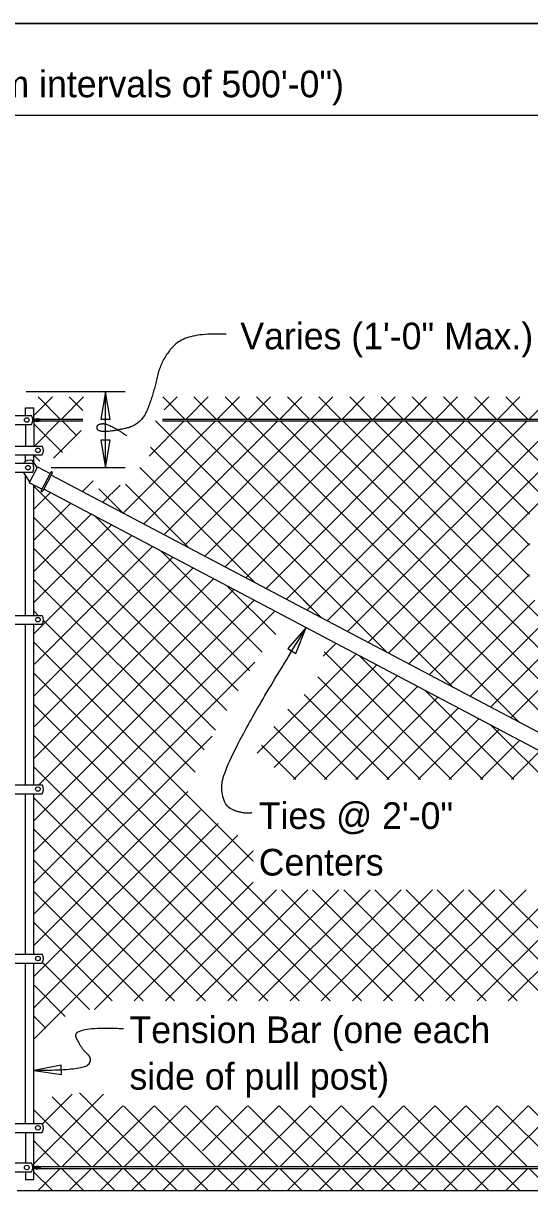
# Model space of a CAD drawing. Extents: x 0 to 41.2, y 0 to 26.
# Drawn here: x 12.4 to 16.23, y 17.08 to 25.96 of the extents above; entities that cross this region are included whole.
import ezdxf

# ---------------------------------------------------------------- set-up
doc = ezdxf.new("R2010")
doc.units = 0
for name, color, linetype in [('ActivePts-ConstElements', 7, 'Continuous'), ('Dimension', 7, 'Continuous'), ('Miscellaneous', 7, 'Continuous'), ('Miscellaneous1', 7, 'Continuous'), ('SteelMisc', 7, 'Continuous'), ('SupstrConc', 7, 'Continuous'), ('TextStructures', 7, 'Continuous')]:
    doc.layers.add(name, color=color, linetype=linetype)

msp = doc.modelspace()

# ---------------------------------------------------------------- linework, layer by layer
at = {"layer": 'ActivePts-ConstElements'}
msp.add_lwpolyline([(0, 0), (41.2106, 0), (41.2106, 25.96), (0, 25.96)], close=True, dxfattribs=at)
at = {"layer": 'Dimension'}
for p, q in [((2.2062, 25.2672), (22.2062, 25.2672)), ((13.1684, 23.1761), (12.4194, 23.1761)), ((13.0184, 22.6012), (13.0184, 23.1761)), ((13.1684, 22.6012), (12.6093, 22.6012))]:
    msp.add_line(p, q, dxfattribs=at)
for points in [[(13.0184, 23.1761), (12.9832, 22.9678), (13.0537, 22.9678)], [(13.0184, 22.6012), (13.0537, 22.8095), (12.9832, 22.8095)], [(14.5361, 21.3922), (14.3971, 21.2332), (14.4572, 21.1963)], [(12.4771, 18.0429), (12.6863, 18.0139), (12.6842, 18.0844)]]:
    msp.add_lwpolyline(points, close=True, dxfattribs=at)
for points in [[(13.9321, 23.6099), (13.634, 23.6259), (13.4393, 23.4234), (13.3796, 23.1471), (13.2873, 22.9252), (13.0658, 22.8744), (12.9551, 22.8744), (12.9551, 22.9344), (13.0474, 22.9344), (13.1812, 22.842)], [(14.1244, 19.9926), (14.0777, 19.9785), (13.8948, 20.0458), (13.9033, 20.3724), (14.5362, 21.3922)], [(13.1545, 18.3586), (12.7557, 18.3765), (12.8361, 18.2097), (12.9224, 18.1322), (12.8539, 18.0428), (12.4771, 18.0428)]]:
    msp.add_open_spline(points, degree=2, dxfattribs=at)
at = {"layer": 'Miscellaneous'}
for p, q in [((12.4771, 22.996), (12.6172, 23.1361)), ((12.5097, 23.1361), (12.6764, 22.9695)), ((12.6862, 22.9695), (12.8529, 23.1361)), ((12.7454, 23.1361), (12.8477, 23.0339)), ((13.4525, 23.1361), (13.6192, 22.9695)), ((13.463, 23.0391), (13.56, 23.1361)), ((13.629, 22.9695), (13.7957, 23.1361)), ((13.6882, 23.1361), (13.8549, 22.9695)), ((13.8647, 22.9695), (14.0314, 23.1361)), ((13.9239, 23.1361), (14.0906, 22.9695)), ((14.1004, 22.9695), (14.2671, 23.1361)), ((14.1597, 23.1361), (14.3263, 22.9695)), ((14.3361, 22.9695), (14.5028, 23.1361)), ((14.3954, 23.1361), (14.562, 22.9695)), ((14.5718, 22.9695), (14.7385, 23.1361)), ((14.6311, 23.1361), (14.7977, 22.9695)), ((14.8075, 22.9695), (14.9742, 23.1361)), ((14.8668, 23.1361), (15.0334, 22.9695)), ((15.0432, 22.9695), (15.2099, 23.1361)), ((15.1025, 23.1361), (15.2691, 22.9695)), ((15.2789, 22.9695), (15.4456, 23.1361)), ((15.3382, 23.1361), (15.5048, 22.9695)), ((15.5146, 22.9695), (15.6813, 23.1361)), ((15.5739, 23.1361), (15.7405, 22.9695)), ((15.7503, 22.9695), (15.917, 23.1361)), ((15.8096, 23.1361), (15.9762, 22.9695)), ((15.986, 22.9695), (16.1527, 23.1361)), ((16.0453, 23.1361), (16.2119, 22.9695)), ((16.2217, 22.9695), (16.3884, 23.1361)), ((12.4771, 22.9331), (12.6938, 22.7164)), ((12.4821, 22.7653), (12.6715, 22.9547)), ((12.6912, 22.9547), (12.7998, 22.8461)), ((13.1537, 22.2584), (13.85, 22.9547)), ((13.3079, 22.177), (14.0857, 22.9547)), ((13.3487, 22.6891), (13.6143, 22.9547)), ((13.3983, 22.9547), (15.1489, 21.2041)), ((13.4621, 22.0955), (14.3214, 22.9547)), ((13.6163, 22.014), (14.5571, 22.9547)), ((13.634, 22.9547), (15.6487, 20.94)), ((13.7706, 21.9325), (14.7928, 22.9547)), ((13.8697, 22.9547), (16.1486, 20.6758)), ((13.9248, 21.851), (15.0285, 22.9547)), ((14.079, 21.7695), (15.2642, 22.9547)), ((14.1054, 22.9547), (16.6484, 20.4117)), ((14.2332, 21.688), (15.4999, 22.9547)), ((14.3411, 22.9547), (17.1483, 20.1475)), ((14.3874, 21.6065), (15.7356, 22.9547)), ((14.5416, 21.525), (15.9713, 22.9547)), ((14.5768, 22.9547), (17.4573, 20.0742)), ((14.6958, 21.4435), (16.207, 22.9547)), ((14.8125, 22.9547), (17.4573, 20.3099)), ((14.85, 21.362), (16.4427, 22.9547)), ((15.0042, 21.2805), (16.6784, 22.9547)), ((15.0482, 22.9547), (16.224, 21.7789)), ((15.1584, 21.199), (16.9141, 22.9547)), ((15.2839, 22.9547), (16.224, 22.0146)), ((15.5196, 22.9547), (16.224, 22.2503)), ((15.7553, 22.9547), (16.393, 22.317)), ((15.991, 22.9547), (16.6287, 22.317)), ((12.625, 22.6726), (12.8347, 22.8823)), ((13.3596, 22.7577), (14.649, 21.4683)), ((12.4771, 22.6974), (12.5225, 22.6519)), ((13.2788, 22.6027), (14.1492, 21.7324)), ((12.4771, 22.4617), (14.0233, 20.9155)), ((12.8453, 22.4214), (12.9257, 22.5019)), ((12.9995, 22.3399), (13.1301, 22.4705)), ((13.1699, 22.476), (13.6493, 21.9966)), ((12.4771, 22.2889), (12.6023, 22.4142)), ((12.9688, 22.4413), (13.1494, 22.2607)), ((12.4771, 22.0532), (12.7565, 22.3327)), ((12.4771, 21.8175), (12.9108, 22.2512)), ((12.4771, 22.226), (13.9369, 20.7661)), ((12.9373, 22.2372), (14.1096, 21.0648)), ((12.4771, 21.5818), (13.065, 22.1697)), ((12.4771, 21.3461), (13.2192, 22.0882)), ((15.3127, 21.1175), (16.224, 22.0289)), ((12.4771, 21.9903), (13.8506, 20.6168)), ((12.4771, 20.8747), (13.5276, 21.9252)), ((12.4835, 21.1168), (13.3734, 22.0067)), ((13.4371, 21.973), (14.2041, 21.206)), ((12.4771, 20.639), (13.6818, 21.8437)), ((12.4771, 20.4033), (13.836, 21.7622)), ((12.4771, 21.7546), (13.7642, 20.4674)), ((15.4669, 21.0361), (16.224, 21.7932)), ((12.5138, 20.2043), (13.9902, 21.6807)), ((13.937, 21.7089), (14.3067, 21.3392)), ((12.4771, 19.9319), (14.1444, 21.5993)), ((14.5173, 21.6), (14.649, 21.4683)), ((15.6211, 20.9546), (16.2665, 21.6)), ((15.7753, 20.8731), (16.5022, 21.6)), ((15.7753, 20.8731), (16.5022, 21.6)), ((15.9295, 20.7916), (16.7379, 21.6)), ((15.9295, 20.7916), (16.7379, 21.6)), ((16.0837, 20.7101), (16.9736, 21.6)), ((16.0837, 20.7101), (16.9736, 21.6)), ((12.4771, 21.5189), (12.5111, 21.4848)), ((12.4771, 19.6962), (14.2987, 21.5178)), ((12.5494, 21.4465), (13.6969, 20.2991)), ((12.4771, 21.2832), (14.1345, 19.6257)), ((14.6643, 21.1763), (14.7613, 21.2733)), ((12.4771, 19.4605), (14.1483, 21.1317)), ((14.1658, 20.4421), (14.9155, 21.1918)), ((14.6726, 21.2089), (15.6365, 20.2451)), ((14.9366, 21.1806), (15.8722, 20.2451)), ((12.4771, 21.0475), (14.9544, 18.5701)), ((14.2953, 20.3359), (15.0697, 21.1103)), ((14.4402, 20.2451), (15.2239, 21.0288)), ((14.6248, 21.0211), (15.4008, 20.2451)), ((14.5225, 20.8877), (15.1651, 20.2451)), ((14.6759, 20.2451), (15.3781, 20.9473)), ((14.9116, 20.2451), (15.5323, 20.8658)), ((15.4365, 20.9165), (16.1079, 20.2451)), ((12.4771, 20.8118), (14.7187, 18.5701)), ((14.3976, 20.7769), (14.9294, 20.2451)), ((15.1473, 20.2451), (15.6866, 20.7843)), ((15.383, 20.2451), (15.8408, 20.7028)), ((14.2931, 20.6457), (14.6937, 20.2451)), ((15.6187, 20.2451), (15.995, 20.6214)), ((15.9363, 20.6524), (19.2711, 17.3175)), ((12.4771, 20.5761), (14.483, 18.5701)), ((12.4771, 19.2248), (13.8252, 20.5729)), ((15.8544, 20.2451), (16.1492, 20.5399)), ((14.1993, 20.5038), (14.458, 20.2451)), ((16.0901, 20.2451), (16.3034, 20.4584)), ((12.4771, 20.3404), (14.2473, 18.5701)), ((12.4771, 18.9891), (13.6423, 20.1543)), ((12.4771, 20.1047), (14.0116, 18.5701)), ((12.4771, 18.7534), (13.737, 20.0133)), ((15.5936, 18.5701), (17.0744, 20.0509)), ((12.4771, 18.5177), (13.8698, 19.9104)), ((15.8293, 18.5701), (17.2287, 19.9694)), ((16.065, 18.5701), (17.3829, 19.8879)), ((12.4771, 19.869), (13.7759, 18.5701)), ((12.4771, 18.282), (14.0185, 19.8234)), ((12.4771, 19.6333), (13.5402, 18.5701)), ((12.9361, 18.5053), (14.1345, 19.7037)), ((13.2366, 18.5701), (14.1345, 19.468)), ((12.4771, 19.3976), (13.3045, 18.5701)), ((13.4723, 18.5701), (14.3131, 19.4109)), ((13.708, 18.5701), (14.5488, 19.4109)), ((13.9437, 18.5701), (14.7845, 19.4109)), ((14.1794, 18.5701), (15.0202, 19.4109)), ((14.3493, 19.4109), (15.1901, 18.5701)), ((14.4151, 18.5701), (15.2559, 19.4109)), ((14.585, 19.4109), (15.4258, 18.5701)), ((14.6508, 18.5701), (15.4916, 19.4109)), ((14.8207, 19.4109), (15.6615, 18.5701)), ((14.8865, 18.5701), (15.7274, 19.4109)), ((15.0564, 19.4109), (15.8972, 18.5701)), ((15.1222, 18.5701), (15.9631, 19.4109)), ((15.2921, 19.4109), (16.1329, 18.5701)), ((15.3579, 18.5701), (16.1988, 19.4109)), ((15.5278, 19.4109), (16.3686, 18.5701)), ((15.7635, 19.4109), (17.8569, 17.3175)), ((15.9992, 19.4109), (18.0926, 17.3175)), ((12.4771, 19.1619), (13.0688, 18.5701)), ((12.5429, 18.8603), (12.897, 18.5062)), ((12.4771, 18.6905), (12.715, 18.4525)), ((12.4771, 18.4548), (12.5674, 18.3644)), ((12.4771, 17.3391), (13.0028, 17.8649)), ((12.5428, 17.6406), (12.7683, 17.8661)), ((12.6161, 17.8443), (13.1429, 17.3175)), ((12.8223, 17.8738), (13.3786, 17.3175)), ((12.6912, 17.3175), (13.1513, 17.7777)), ((12.9269, 17.3175), (13.387, 17.7777)), ((13.1541, 17.7777), (13.6143, 17.3175)), ((13.1626, 17.3175), (13.6227, 17.7777)), ((13.3898, 17.7777), (13.85, 17.3175)), ((13.3983, 17.3175), (13.8584, 17.7777)), ((13.6255, 17.7777), (14.0857, 17.3175)), ((13.7518, 17.4354), (14.0941, 17.7777)), ((13.8612, 17.7777), (14.3214, 17.3175)), ((13.8697, 17.3175), (14.3298, 17.7777)), ((14.0969, 17.7777), (14.5571, 17.3175)), ((14.1054, 17.3175), (14.5655, 17.7777)), ((14.3326, 17.7777), (14.7928, 17.3175)), ((14.3411, 17.3175), (14.8012, 17.7777)), ((14.5683, 17.7777), (15.0285, 17.3175)), ((14.5768, 17.3175), (15.0369, 17.7777)), ((14.804, 17.7777), (15.2642, 17.3175)), ((14.8125, 17.3175), (15.2726, 17.7777)), ((15.0397, 17.7777), (15.4999, 17.3175)), ((15.0482, 17.3175), (15.5083, 17.7777)), ((15.2754, 17.7777), (15.7356, 17.3175)), ((15.2839, 17.3175), (15.744, 17.7777)), ((15.5111, 17.7777), (15.9713, 17.3175)), ((15.5196, 17.3175), (15.9797, 17.7777)), ((15.7468, 17.7777), (16.207, 17.3175)), ((15.7553, 17.3175), (16.2155, 17.7777)), ((15.9825, 17.7777), (16.4427, 17.3175)), ((15.991, 17.3175), (16.4503, 17.7768)), ((16.2182, 17.7777), (16.6784, 17.3175)), ((12.4771, 17.7476), (12.9072, 17.3175)), ((12.4771, 17.5119), (12.6715, 17.3175)), ((12.4771, 17.2762), (12.6172, 17.1361)), ((12.5097, 17.1361), (12.6764, 17.3028)), ((12.6862, 17.3028), (12.8529, 17.1361)), ((12.7454, 17.1361), (12.9121, 17.3028)), ((12.9219, 17.3028), (13.0886, 17.1361)), ((12.9811, 17.1361), (13.1478, 17.3028)), ((13.1576, 17.3028), (13.3243, 17.1361)), ((13.2168, 17.1361), (13.3835, 17.3028)), ((13.3933, 17.3028), (13.56, 17.1361)), ((13.4525, 17.1361), (13.6192, 17.3028)), ((13.629, 17.3028), (13.7957, 17.1361)), ((13.6882, 17.1361), (13.8549, 17.3028)), ((13.8647, 17.3028), (14.0314, 17.1361)), ((13.9239, 17.1361), (14.0906, 17.3028)), ((14.1004, 17.3028), (14.2671, 17.1361)), ((14.1597, 17.1361), (14.3263, 17.3028)), ((14.3361, 17.3028), (14.5028, 17.1361)), ((14.3954, 17.1361), (14.562, 17.3028)), ((14.5718, 17.3028), (14.7385, 17.1361)), ((14.6311, 17.1361), (14.7977, 17.3028)), ((14.8075, 17.3028), (14.9742, 17.1361)), ((14.8668, 17.1361), (15.0334, 17.3028)), ((15.0432, 17.3028), (15.2099, 17.1361)), ((15.1025, 17.1361), (15.2691, 17.3028)), ((15.2789, 17.3028), (15.4456, 17.1361)), ((15.3382, 17.1361), (15.5048, 17.3028)), ((15.5146, 17.3028), (15.6813, 17.1361)), ((15.5739, 17.1361), (15.7405, 17.3028)), ((15.7503, 17.3028), (15.917, 17.1361)), ((15.8096, 17.1361), (15.9762, 17.3028)), ((15.986, 17.3028), (16.1527, 17.1361)), ((16.0453, 17.1361), (16.2119, 17.3028)), ((16.2217, 17.3028), (16.3884, 17.1361))]:
    msp.add_line(p, q, dxfattribs=at)
at = {"layer": 'Miscellaneous1'}
msp.add_lwpolyline([(0, 25.96), (41.2106, 25.96), (41.2106, 0), (0, 0)], close=True, dxfattribs=at)
at = {"layer": 'SteelMisc'}
for p, q in [((12.0505, 22.9966), (12.4602, 22.9966)), ((12.4146, 22.9966), (12.4146, 23.0528)), ((12.4146, 23.0528), (12.4771, 23.0528)), ((12.4146, 22.9966), (12.4146, 23.0528)), ((12.4146, 23.0528), (12.4771, 23.0528)), ((12.4771, 22.9726), (12.4771, 23.0528)), ((12.4771, 22.9726), (12.4771, 23.0528)), ((12.0505, 22.9289), (12.4599, 22.9289)), ((12.4146, 22.9288), (12.4146, 22.7653)), ((12.4146, 22.9288), (12.4146, 22.7653)), ((12.4675, 22.9741), (12.4968, 22.9695)), ((12.4676, 22.9741), (12.4969, 22.9695)), ((12.468, 22.9537), (12.5017, 22.9593)), ((12.4681, 22.9691), (12.4942, 22.965)), ((12.4681, 22.9537), (12.5018, 22.9593)), ((12.4682, 22.9691), (12.4943, 22.965)), ((12.4684, 22.9585), (12.4983, 22.9634)), ((12.4685, 22.9585), (12.4984, 22.9634)), ((12.4771, 22.9676), (12.4771, 22.9598)), ((12.4771, 22.9676), (12.4771, 22.9598)), ((12.4771, 22.9552), (12.4771, 22.7653)), ((12.4771, 22.9552), (12.4771, 22.7653)), ((12.4881, 22.9547), (12.8472, 22.9547)), ((12.4894, 22.9695), (12.8472, 22.9695)), ((13.4503, 22.9695), (21.8852, 22.9695)), ((13.4503, 22.9547), (21.9119, 22.9547)), ((12.0505, 22.7654), (12.5416, 22.7654)), ((11.9439, 22.6358), (12.4686, 22.6358)), ((12.0505, 22.6977), (12.5408, 22.6977)), ((12.4146, 22.6487), (12.4146, 22.6977)), ((12.5028, 22.6018), (12.468, 22.6549)), ((12.4771, 22.6411), (12.4771, 22.6977)), ((11.9439, 22.568), (12.4686, 22.568)), ((12.4467, 22.4958), (12.3998, 22.5675)), ((12.5062, 22.6083), (12.4425, 22.4877)), ((12.5062, 22.6083), (12.6005, 22.5585)), ((12.6051, 22.5671), (12.5327, 22.43)), ((12.617, 22.5609), (12.5445, 22.4237)), ((12.4146, 21.4848), (12.4146, 22.545)), ((12.5368, 22.4379), (12.4425, 22.4877)), ((12.4771, 21.4848), (12.4771, 22.4695)), ((21.8588, 17.6582), (12.6092, 22.5462)), ((21.8029, 17.5522), (12.5532, 22.4401)), ((12.4146, 21.4848), (12.4146, 22.0501)), ((12.4771, 21.4848), (12.4771, 22.0155)), ((12.0505, 21.4848), (12.5416, 21.4848)), ((12.0505, 21.4172), (12.5408, 21.4172)), ((12.4146, 20.2043), (12.4146, 21.4172)), ((12.4771, 20.2043), (12.4771, 21.4172)), ((12.0505, 20.2043), (12.5416, 20.2043)), ((12.0505, 20.1367), (12.5408, 20.1367)), ((12.4146, 18.9238), (12.4146, 20.1367)), ((12.4771, 18.9238), (12.4771, 20.1367)), ((12.0505, 18.9238), (12.5416, 18.9238)), ((12.0505, 18.8562), (12.5408, 18.8562)), ((12.4146, 17.6433), (12.4146, 18.8561)), ((12.4771, 17.6433), (12.4771, 18.8561)), ((12.0505, 17.6434), (12.5416, 17.6434)), ((12.0505, 17.5757), (12.5408, 17.5757)), ((12.4146, 17.5757), (12.4146, 17.3447)), ((12.4771, 17.3207), (12.4771, 17.5757)), ((11.9524, 17.3447), (12.4602, 17.3447)), ((12.4675, 17.3222), (12.4968, 17.3176)), ((12.4676, 17.3222), (12.4969, 17.3176)), ((12.4681, 17.3171), (12.4942, 17.3131)), ((12.4682, 17.3171), (12.4943, 17.3131)), ((12.4684, 17.3065), (12.4983, 17.3115)), ((12.4685, 17.3065), (12.4984, 17.3115)), ((12.4771, 17.3079), (12.4771, 17.3157)), ((12.4771, 17.3079), (12.4771, 17.3157)), ((12.5154, 17.3175), (21.8852, 17.3175)), ((11.9526, 17.2769), (12.4599, 17.2769)), ((12.4146, 17.2769), (12.4146, 17.2195)), ((12.468, 17.3018), (12.5017, 17.3074)), ((12.4681, 17.3018), (12.5018, 17.3074)), ((12.4771, 17.2195), (12.4771, 17.3032)), ((12.5141, 17.3028), (21.9119, 17.3028)), ((12.4146, 17.2195), (12.4771, 17.2195))]:
    msp.add_line(p, q, dxfattribs=at)
for centre, start, end in [((12.6109, 22.5639), 332.14902, 152.14902), ((12.5384, 22.4267), 152.14902, 332.14902)]:
    msp.add_arc(centre, 0.00673, start, end, dxfattribs=at)
for centre, major_axis, ratio, start_param, end_param in [((12.3909, 22.963), (0.0776, 0), 0.957868, 5.803915, 6.752041), ((12.3909, 22.963), (0.0776, 0), 0.957868, 5.803915, 6.752041), ((12.4993, 22.9596), (-0.0095, 0), 0.957868, 5.673972, 6.052579), ((12.4993, 22.9596), (-0.0095, 0), 0.957868, 5.673972, 6.052579), ((12.4993, 22.9596), (-0.0095, 0), 0.957868, 0.252467, 1.271421), ((12.4993, 22.9596), (-0.0095, 0), 0.957868, 0.252467, 1.271421), ((12.4953, 22.9604), (0.0115, -0.0041), 0.737732, 5.08821, 8.212701), ((12.4953, 22.9604), (0.0115, -0.0041), 0.737732, 5.08821, 8.212701), ((12.4934, 22.9555), (0.00982, 0), 0.957868, 0.655696, 1.505671), ((12.4934, 22.9555), (0.00982, 0), 0.957868, 0.655696, 1.505671), ((12.4988, 22.9579), (0.00301, 0), 0.957868, 3.28349, 5.170635), ((12.4988, 22.9579), (0.00301, 0), 0.957868, 3.28349, 5.170635), ((12.4994, 22.9601), (-0.00453, 0), 0.957868, 5.149727, 5.551998), ((12.4994, 22.9601), (-0.00453, 0), 0.957868, 5.149727, 5.551998), ((12.4966, 22.9588), (0.00527, 0), 0.957868, 5.058829, 7.342751), ((12.4966, 22.9588), (0.00527, 0), 0.957868, 5.058829, 7.342751), ((12.501, 22.9612), (-0.00872, 0), 0.957868, 2.1008, 4.992926), ((12.501, 22.9612), (-0.00872, 0), 0.957868, 2.1008, 4.992926), ((12.4988, 22.9579), (0.00301, 0), 0.957868, 0.004594, 0.141897), ((12.4988, 22.9579), (0.00301, 0), 0.957868, 0.004594, 0.141897), ((12.5071, 22.9608), (0.00944, 0), 0.957868, 4.316497, 6.557353), ((12.5071, 22.9608), (0.00944, 0), 0.957868, 4.316497, 6.557353), ((12.5076, 22.9617), (-0.00872, 0), 0.957868, 3.323334, 4.992926), ((12.5076, 22.9617), (-0.00872, 0), 0.957868, 3.323334, 4.992926), ((12.5076, 22.9617), (-0.00503, 0), 0.92697, 1.780895, 4.712389), ((12.5076, 22.9617), (-0.00503, 0), 0.92697, 1.780895, 4.712389), ((12.5123, 22.9562), (-0.0142, 0), 0.957868, 3.141593, 4.79635), ((12.5123, 22.9562), (-0.0142, 0), 0.957868, 3.141593, 4.79635), ((12.5043, 22.9412), (0.0274, 0), 0.957868, 0.628521, 1.149654), ((12.5043, 22.9412), (0.0274, 0), 0.957868, 0.628521, 1.149654), ((12.472, 22.7322), (0.0776, 0), 0.957868, 5.801244, 6.745158), ((12.472, 22.7322), (0.0776, 0), 0.957868, 5.801244, 6.745158), ((12.4514, 22.5866), (-0.0647, 0.0342), 0.957868, 4.95193, 6.011789), ((12.3994, 22.6016), (0.0776, 0), 0.957868, 5.810211, 6.75616), ((12.472, 21.4517), (0.0776, 0), 0.957868, 5.801046, 6.744962), ((12.472, 21.4517), (0.0776, 0), 0.957868, 5.801046, 6.744962), ((12.472, 20.1712), (0.0776, 0), 0.957868, 5.800848, 6.744767), ((12.472, 20.1712), (0.0776, 0), 0.957868, 5.800848, 6.744767), ((12.472, 18.8906), (0.0776, 0), 0.957868, 5.810211, 6.745158), ((12.472, 18.8906), (0.0776, 0), 0.957868, 5.810211, 6.745158), ((12.472, 17.6101), (0.0776, 0), 0.957868, 5.800651, 6.745353), ((12.3909, 17.311), (0.0776, 0), 0.957868, 5.803915, 6.752041), ((12.3909, 17.311), (0.0776, 0), 0.957868, 5.803915, 6.752041), ((12.4993, 17.3077), (-0.0095, 0), 0.957868, 5.673972, 6.052579), ((12.4993, 17.3077), (-0.0095, 0), 0.957868, 5.673972, 6.052579), ((12.4953, 17.3084), (0.0115, -0.0041), 0.737732, 5.08821, 8.212701), ((12.4953, 17.3084), (0.0115, -0.0041), 0.737732, 5.08821, 8.212701), ((12.4934, 17.3035), (0.00982, 0), 0.957868, 0.655696, 1.505671), ((12.4934, 17.3035), (0.00982, 0), 0.957868, 0.655696, 1.505671), ((12.4994, 17.3082), (-0.00453, 0), 0.957868, 5.149727, 5.551998), ((12.4994, 17.3082), (-0.00453, 0), 0.957868, 5.149727, 5.551998), ((12.4966, 17.3069), (0.00527, 0), 0.957868, 5.058829, 7.342751), ((12.4966, 17.3069), (0.00527, 0), 0.957868, 5.058829, 7.342751), ((12.501, 17.3093), (-0.00872, 0), 0.957868, 2.1008, 4.992926), ((12.501, 17.3093), (-0.00872, 0), 0.957868, 2.1008, 4.992926), ((12.5071, 17.3089), (0.00944, 0), 0.957868, 4.316497, 6.557353), ((12.5071, 17.3089), (0.00944, 0), 0.957868, 4.316497, 6.557353), ((12.5076, 17.3098), (-0.00872, 0), 0.957868, 3.323334, 4.992926), ((12.5076, 17.3098), (-0.00872, 0), 0.957868, 3.323334, 4.992926), ((12.5076, 17.3098), (-0.00503, 0), 0.92697, 1.780895, 4.712389), ((12.5076, 17.3098), (-0.00503, 0), 0.92697, 1.780895, 4.712389), ((12.5123, 17.3043), (-0.0142, 0), 0.957868, 3.141593, 4.79635), ((12.5123, 17.3043), (-0.0142, 0), 0.957868, 3.141593, 4.79635), ((12.5043, 17.2893), (0.0274, 0), 0.957868, 0.628521, 1.149654), ((12.5043, 17.2893), (0.0274, 0), 0.957868, 0.628521, 1.149654), ((12.4993, 17.3077), (-0.0095, 0), 0.957868, 0.252467, 1.271421), ((12.4993, 17.3077), (-0.0095, 0), 0.957868, 0.252467, 1.271421), ((12.4988, 17.306), (0.00301, 0), 0.957868, 3.28349, 5.170635), ((12.4988, 17.306), (0.00301, 0), 0.957868, 3.28349, 5.170635), ((12.4988, 17.306), (0.00301, 0), 0.957868, 0.004594, 0.141897), ((12.4988, 17.306), (0.00301, 0), 0.957868, 0.004594, 0.141897)]:
    msp.add_ellipse(centre, major_axis=major_axis, ratio=ratio, start_param=start_param, end_param=end_param, dxfattribs=at)
for centre, major_axis in [((12.4242, 22.9621), (-0.0178, 0)), ((12.4242, 22.9621), (-0.0178, 0)), ((12.5079, 22.7326), (-0.0177, 0)), ((12.5079, 22.7326), (-0.0177, 0)), ((12.4327, 22.6012), (-0.0178, 0)), ((12.5079, 21.4521), (-0.0177, 0)), ((12.5079, 21.4521), (-0.0177, 0)), ((12.5079, 20.1716), (-0.0177, 0)), ((12.5079, 20.1716), (-0.0177, 0)), ((12.5079, 18.891), (-0.0177, 0)), ((12.5079, 18.891), (-0.0177, 0)), ((12.5079, 17.6106), (-0.0177, 0)), ((12.4242, 17.3102), (-0.0178, 0)), ((12.4242, 17.3102), (-0.0178, 0))]:
    msp.add_ellipse(centre, major_axis=major_axis, ratio=0.957868, dxfattribs=at)
at = {"layer": 'SupstrConc'}
msp.add_line((12.3521, 17.1361), (18.8204, 17.1361), dxfattribs=at)

# ---------------------------------------------------------------- texts
at = {"layer": 'TextStructures'}
for s, p in [('Pull Post Assembly (required at maximum intervals of 500\'-0")', (7.4383, 25.402)), ('Varies (1\'-0" Max.)  (Typ.)', (14.0385, 23.4963)), ('Ties @ 2\'-0" ', (14.1779, 19.8699)), ('Centers', (14.1779, 19.5179)), ('Tension Bar (one each ', (13.2005, 18.2509)), ('side of pull post)', (13.2005, 17.8989))]:
    msp.add_text(s, height=0.2016, dxfattribs=at).set_placement(p)

doc.saveas('drawing.dxf')
